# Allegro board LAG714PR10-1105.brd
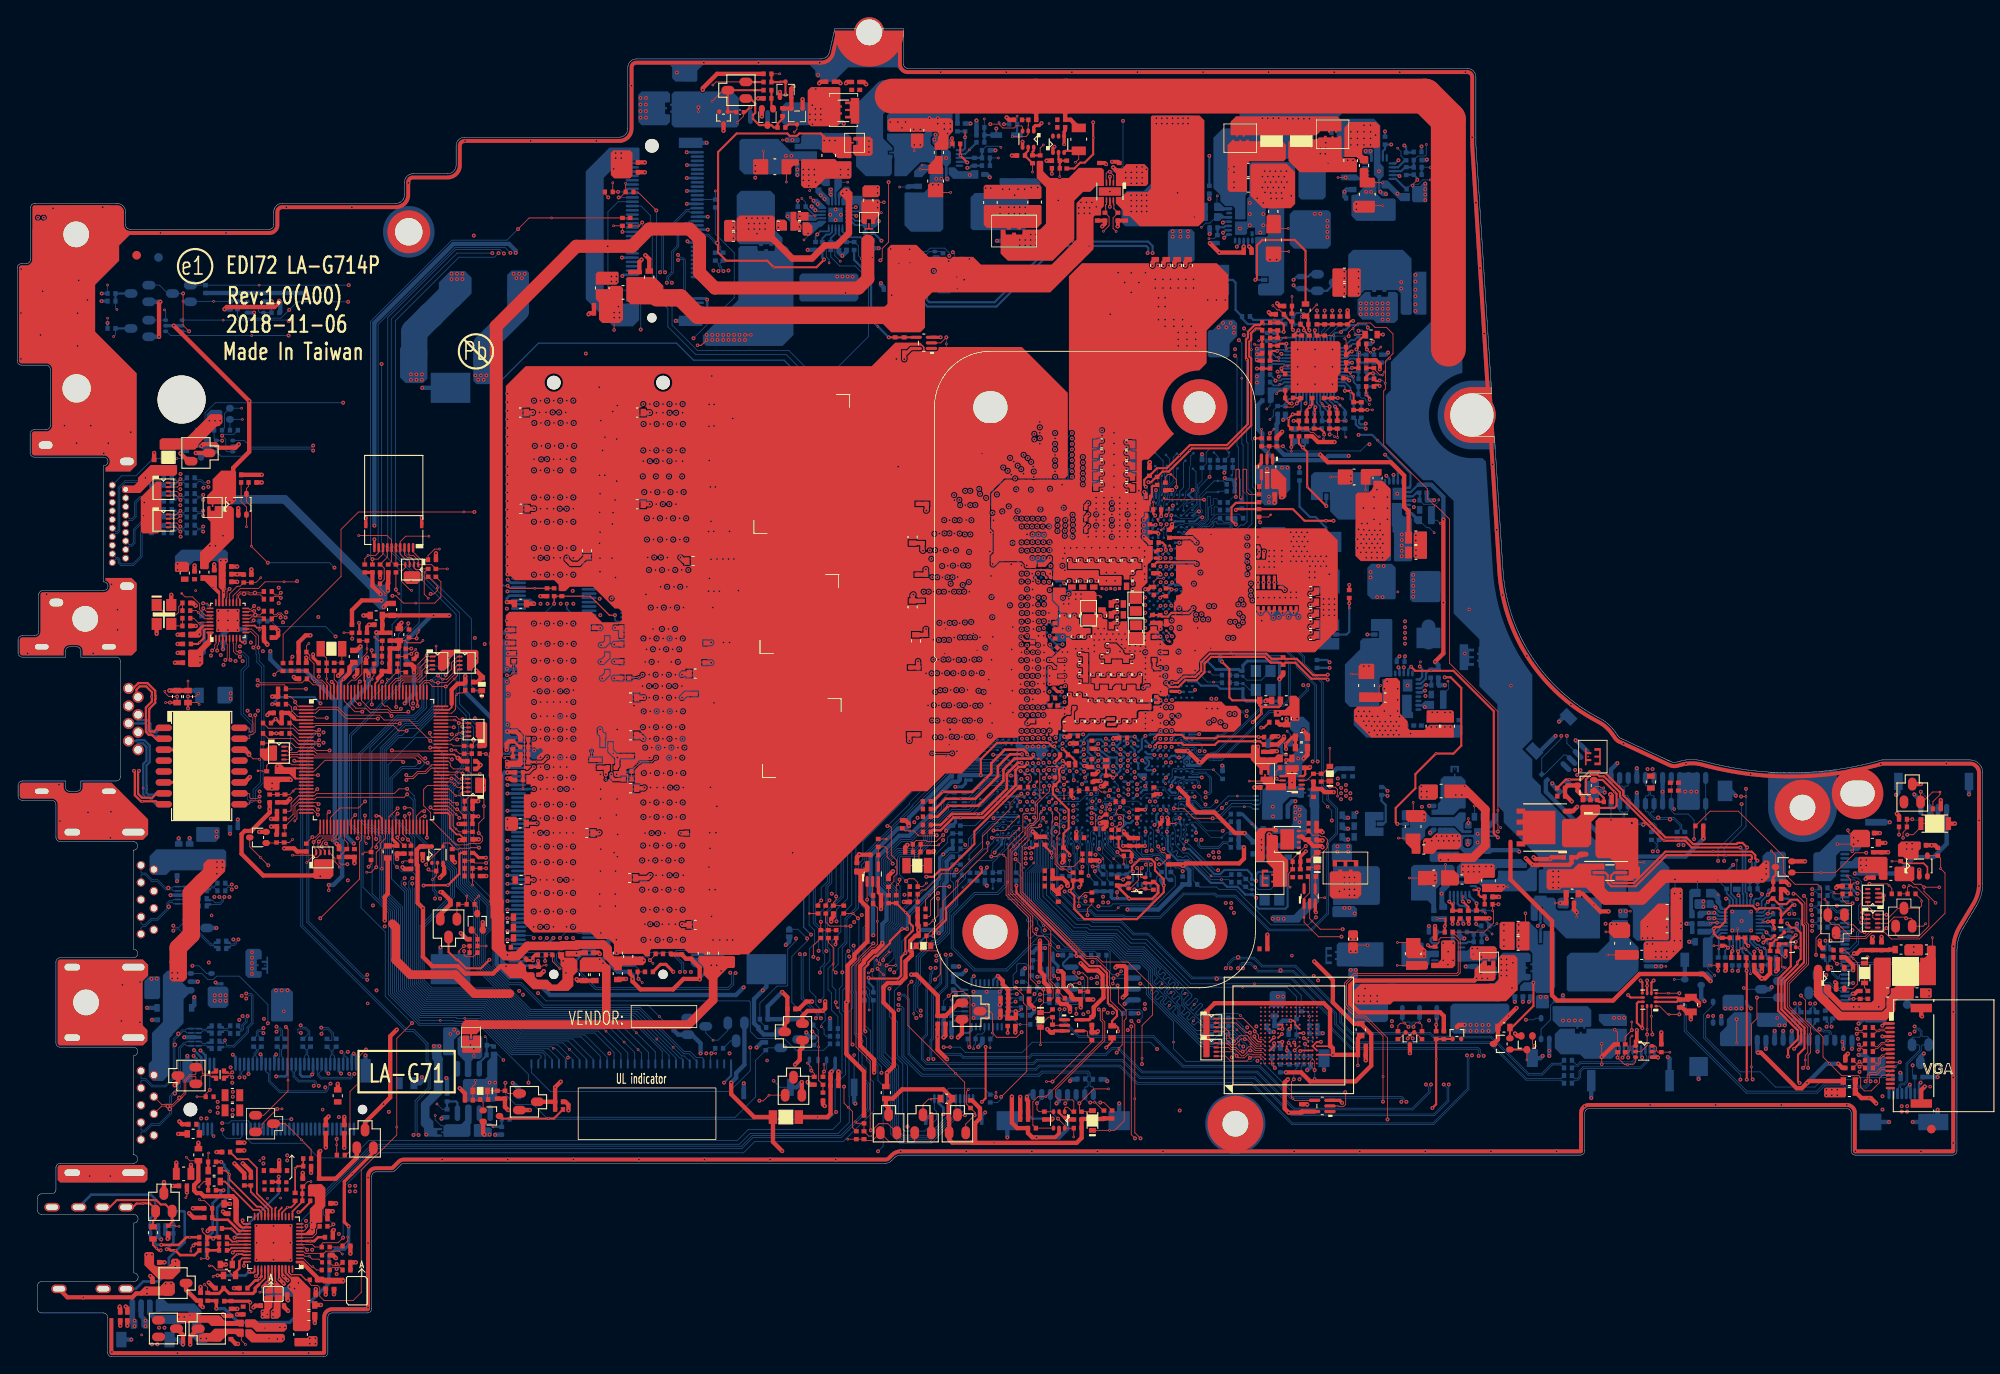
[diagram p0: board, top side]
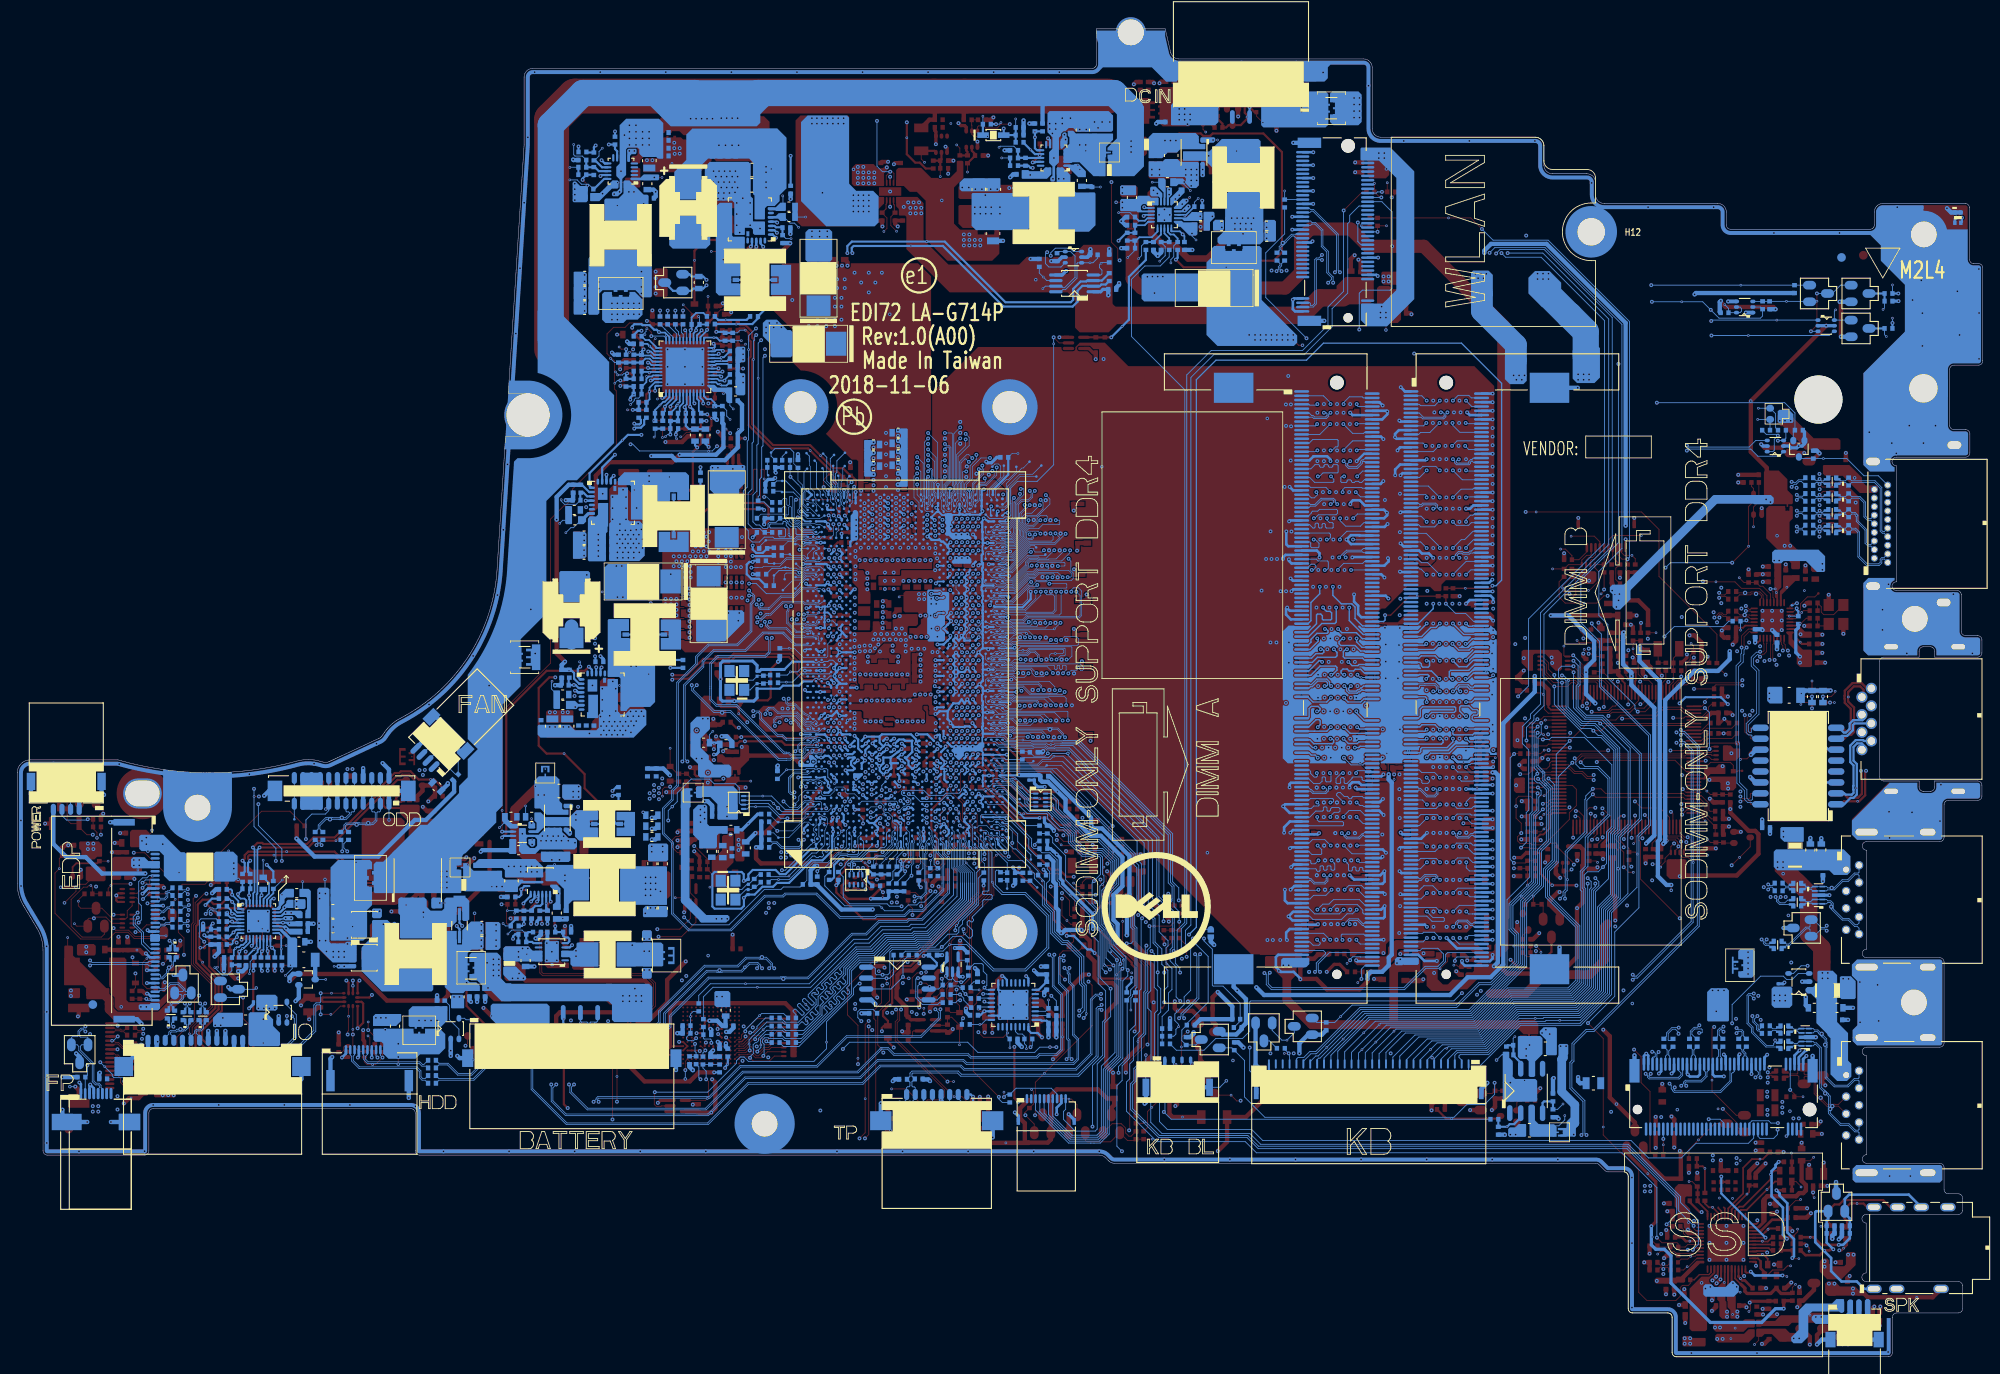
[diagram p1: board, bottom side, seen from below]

Outline 228.4 x 154.4 mm; copper layers: TOP, VCC, IN1, IN2, GND, BOTTOM. Coordinates in mm from the lower left corner of the outline.
Outline path: 0,126.6 arc(0.15,126.95) 0.5,127.1 1.05,127.1 arc(1.4,127.25) 1.55,127.6 1.55,133.6 arc(1.7,133.95) 2.05,134.1 11.6,134.1 arc(12.31,133.81) 12.6,133.1 12.6,131.6 arc(12.75,131.25) 13.1,131.1 29.3,131.1 arc(29.65,131.25) 29.8,131.6 29.8,133.1 arc(30.09,133.81) 30.8,134.1 44,134.1 arc(44.71,134.39) 45,135.1 45,136.55 arc(45.29,137.26) 46,137.55 50,137.55 arc(50.71,137.84) 51,138.55 51,140.8 arc(51.29,141.51) 52,141.8 69.95,141.8 arc(70.66,142.09) 70.95,142.8 70.95,149.9 arc(71.24,150.61) 71.95,150.9 93.4,150.9 arc(94.03,151.12) 94.38,151.68 95,154.4 97.5,154.4 97.5,154 arc(99,152.5) 100.5,154 100.5,154.4 103,154.4 103,150.3 arc(103.15,149.95) 103.5,149.8 168.5,149.8 arc(169.21,149.51) 169.5,148.8 169.5,140.9 171.34,112 169.05,112 arc(166.55,109.5) 169.05,107 171.66,107 172.64,91.52 arc(176,81.39) 183.91,74.22 arc(184.91,73.53) 185.72,72.62 185.99,72.22 arc(186.17,72.03) 186.39,71.89 192.15,69.2 arc(192.5,69.11) 192.85,69.14 193.21,69.25 arc(194.56,69.44) 195.9,69.26 arc(206.31,67.9) 216.69,69.4 226.9,69.4 arc(227.96,68.96) 228.4,67.9 228.4,55.03 arc(228.22,53.7) 227.69,52.46 226.11,49.84 arc(225.58,48.6) 225.4,47.27 225.4,23.95 arc(225.25,23.6) 224.9,23.45 213.6,23.45 arc(213.25,23.6) 213.1,23.95 213.1,28.35 arc(212.95,28.7) 212.6,28.85 182.65,28.85 arc(182.3,28.7) 182.15,28.35 182.15,23.95 arc(182,23.6) 181.65,23.45 102.66,23.45 arc(102.28,23.37) 101.96,23.16 101.59,22.79 arc(101.27,22.58) 100.89,22.5 44.96,22.5 arc(44.77,22.46) 44.6,22.35 43.9,21.65 arc(43.73,21.54) 43.54,21.5 41.7,21.5 arc(41.35,21.35) 41.2,21 41.2,5.6 arc(41.05,5.25) 40.7,5.1 36.6,5.1 arc(36.25,4.95) 36.1,4.6 36.1,0.5 arc(35.95,0.15) 35.6,0 11,0 arc(10.65,0.15) 10.5,0.5 10.5,4.6 arc(10.35,4.95) 10,5.1 2.85,5.1 arc(2.5,5.25) 2.35,5.6 2.35,8.25 arc(2.5,8.6) 2.85,8.75 13.55,8.75 arc(14.05,9.25) 13.55,9.75 13.55,15.55 arc(14.05,16.05) 13.55,16.55 2.85,16.55 arc(2.5,16.7) 2.35,17.05 2.35,18.45 arc(2.5,18.8) 2.85,18.95 4,18.95 arc(4.35,19.1) 4.5,19.45 4.5,22 arc(4.65,22.35) 5,22.5 13.5,22.5 arc(14,23) 13.5,23.5 13.5,35 arc(14,35.5) 13.5,36 5,36 arc(4.65,36.15) 4.5,36.5 4.5,45.9 arc(4.65,46.25) 5,46.4 13.5,46.4 arc(14,46.9) 13.5,47.4 13.5,58.9 arc(14,59.4) 13.5,59.9 5,59.9 arc(4.65,60.05) 4.5,60.4 4.5,64.2 arc(4.35,64.55) 4,64.7 0.6,64.7 arc(0.25,64.85) 0.1,65.2 0.1,66.45 arc(0.25,66.8) 0.6,66.95 5.6,66.95 5.6,66.25 arc(5.75,65.9) 6.1,65.75 6.9,65.75 arc(7.25,65.9) 7.4,66.25 7.4,66.95 11.5,66.95 arc(11.85,67.1) 12,67.45 12,80.85 arc(11.85,81.2) 11.5,81.35 7.4,81.35 7.4,82.05 arc(7.25,82.4) 6.9,82.55 6.1,82.55 arc(5.75,82.4) 5.6,82.05 5.6,81.35 0.6,81.35 arc(0.25,81.5) 0.1,81.85 0.1,83.35 arc(0.25,83.7) 0.6,83.85 2,83.85 arc(2.35,84) 2.5,84.35 2.5,88.6 arc(2.65,88.95) 3,89.1 10.05,89.1 arc(10.55,89.6) 10.05,90.1 10.05,103.6 arc(10.55,104.1) 10.05,104.6 2,104.6 arc(1.65,104.75) 1.5,105.1 1.5,107.3 arc(1.65,107.65) 2,107.8 3.35,107.8 arc(3.7,107.95) 3.85,108.3 3.85,114.8 arc(3.7,115.15) 3.35,115.3 0.5,115.3 arc(0.15,115.45) 0,115.8 0,126.6

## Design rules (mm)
net group AS-PROCHOT#: nets H_PROCHOT# H_PROCHOT#_R
net group AS-VCCST_PWRGOOD: nets H_VCCST_PWRGD VCCST_PWRGD
net group CLK_PCIE_NVME_4: nets CLK_PCIE_NVME_N4 CLK_PCIE_NVME_P4
net group CPU-DP: nets CPU_DP2_AUXN CPU_DP2_AUXP
net group CPU_DP1_CTRL_CLK: nets CPU_DP1_CTRL_CLK CPU_DP1_CTRL_DATA
net group CPU_DP2_0: nets CPU_DP2_N0 CPU_DP2_P0
net group CPU_DP2_0_C: nets CPU_DP2_N0_C CPU_DP2_P0_C
net group CPU_DP2_1: nets CPU_DP2_N1 CPU_DP2_P1
net group CPU_DP2_1_C: nets CPU_DP2_N1_C CPU_DP2_P1_C
net group CPU_DP2_AUX_C: nets CPU_DP2_AUXN_C CPU_DP2_AUXP_C
net group DDR_A_CLK0: nets DDR_A_CLK0 DDR_A_CLK#0
net group DDR_A_CLK1: nets DDR_A_CLK1 DDR_A_CLK#1
net group DDR_B_CLK0: nets DDR_B_CLK0 DDR_B_CLK#0
net group DDR_B_CLK1: nets DDR_B_CLK1 DDR_B_CLK#1
net group DDR_RESET: nets DDR4_DRAMRST# H_DRAMRST#
net group DMIC_EDP: nets DMIC_CLK_EDP DMIC_DATA_EDP
net group EDP_AUX: nets EDP_AUX EDP_AUX#
net group EDP_AUX_D: nets EDP_AUX_DN EDP_AUX_DP
net group EDP_TX0: nets EDP_TX0 EDP_TX0#
net group EDP_TX0_D: nets EDP_TX0_DN EDP_TX0_DP
net group EDP_TX1: nets EDP_TX1 EDP_TX1#
net group EDP_TX1_D: nets EDP_TX1_DN EDP_TX1_DP
net group HDA_CBN/CBP/CPVEE: nets CBP CPVEE
net group HDMI_CLK: nets HDMI_CLK HDMI_CLK#
net group HDMI_CLK_R: nets HDMI_CLK#_R HDMI_CLK_R
net group HDMI_CLK_R_C: nets HDMI_CLK#_R_C HDMI_CLK_R_C
net group HDMI_DATA0: nets HDMI_DATA0 HDMI_DATA0#
net group HDMI_DATA0_R: nets HDMI_DATA0#_R HDMI_DATA0_R
net group HDMI_DATA0_R_C: nets HDMI_DATA0#_R_C HDMI_DATA0_R_C
net group HDMI_DATA1: nets HDMI_DATA1 HDMI_DATA1#
net group HDMI_DATA1_R: nets HDMI_DATA1#_R HDMI_DATA1_R
net group HDMI_DATA1_R_C: nets HDMI_DATA1#_R_C HDMI_DATA1_R_C
net group HDMI_DATA2: nets HDMI_DATA2 HDMI_DATA2#
net group HDMI_DATA2_R: nets HDMI_DATA2#_R HDMI_DATA2_R
net group HDMI_DATA2_R_C: nets HDMI_DATA2#_R_C HDMI_DATA2_R_C
net group HDMI_DDC: nets DDC_CLK_HDMI DDC_DATA_HDMI
net group I2C: nets CLK_TP_SIO DAT_TP_SIO
net group I2C0_SCL_TCH_PAD: nets I2C0_SCL_TCH_PAD I2C0_SDA_TCH_PAD
net group I2C_SCL_TP: nets I2C_SCL_TP I2C_SDA_TP
net group LAN_MDI2: nets LAN_MDI2N LAN_MDI2P
net group LAN_MDI3: nets LAN_MDI3N LAN_MDI3P
net group MDO2: nets MDO2+ MDO2-
net group MDO3: nets MDO3+ MDO3-
net group NCT7718_DXP: nets NCT7718_DXN NCT7718_DXP
net group PCH_SMBCLK: nets PCH_SMBCLK PCH_SMBDATA
net group PCIE_CRX_NVMETX_9: nets PCIE_CRX_NVMETX_N9 PCIE_CRX_NVMETX_P9
net group PCIE_CRX_NVMETX_10: nets PCIE_CRX_NVMETX_N10 PCIE_CRX_NVMETX_P10
net group PCIE_CRX_NVMETX_11: nets PCIE_CRX_NVMETX_N11 PCIE_CRX_NVMETX_P11
net group PCIE_CRX_NVMETX_12: nets PCIE_CRX_NVMETX_N12 PCIE_CRX_NVMETX_P12
net group PCIE_CRX_WLANTX_6: nets PCIE_CRX_WLANTX_N6 PCIE_CRX_WLANTX_P6
net group PCIE_CTX_C_LANRX_5: nets PCIE_CTX_C_LANRX_N5 PCIE_CTX_C_LANRX_P5
net group PCIE_CTX_C_NVMERX_9: nets PCIE_CTX_C_NVMERX_N9 PCIE_CTX_C_NVMERX_P9
net group PCIE_CTX_C_NVMERX_11: nets PCIE_CTX_C_NVMERX_N11 PCIE_CTX_C_NVMERX_P11
net group PCIE_CTX_C_NVMERX_12: nets PCIE_CTX_C_NVMERX_N12 PCIE_CTX_C_NVMERX_P12
net group PCIE_CTX_C_WLANRX_6: nets PCIE_CTX_C_WLANRX_N6 PCIE_CTX_C_WLANRX_P6
net group PCIE_CTX_LANRX_5: nets PCIE_CTX_LANRX_N5 PCIE_CTX_LANRX_P5
net group PCIE_CTX_NVMERX_9: nets PCIE_CTX_NVMERX_N9 PCIE_CTX_NVMERX_P9
net group PCIE_CTX_NVMERX_10: nets PCIE_CTX_NVMERX_N10 PCIE_CTX_NVMERX_P10
net group PCIE_CTX_NVMERX_11: nets PCIE_CTX_NVMERX_N11 PCIE_CTX_NVMERX_P11
net group PCIE_CTX_NVMERX_12: nets PCIE_CTX_NVMERX_N12 PCIE_CTX_NVMERX_P12
net group SATA3_CRX_C_HDDTX_0: nets SATA3_CRX_C_HDDTX_N0 SATA3_CRX_C_HDDTX_P0
net group SATA3_CTX_C_HDDRX_0: nets SATA3_CTX_C_HDDRX_N0 SATA3_CTX_C_HDDRX_P0
net group SML0_SMBCLK: nets SML0_SMBCLK SML0_SMBDATA
net group THM_SML1_CLK: nets THM_SML1_CLK THM_SML1_DATA
net group USB3_CRX_DTX_1_C: nets USB3_CRX_DTX_N1_C USB3_CRX_DTX_P1_C
net group USB3_CTX_DRX_1: nets USB3_CTX_DRX_N1 USB3_CTX_DRX_P1
net group USB3_CTX_DRX_1_C: nets USB3_CTX_DRX_N1_C USB3_CTX_DRX_P1_C
net group USB3_CTX_DRX_1_R: nets USB3_CTX_DRX_N1_R USB3_CTX_DRX_P1_R
net group USB_CAMERA_EDP: nets USB_CAMERA_EDP USB_CAMERA_EDP#
net group USB_P5: nets USB_PN5 USB_PP5
net group USB_P6_R: nets USB_PN6_R USB_PP6_R
net group USB_P7: nets USB_PN7 USB_PP7
net group USB_P9: nets USB_PN9 USB_PP9
net group 15: nets XTAL24_IN_R
net group AS-BPM#[3:0]: nets XDP_OBS0_R XDP_OBS1_R XDP_OBS2_R XDP_OBS3_R
net group AS-CATERR#: nets H_CATERR#
net group AS-PECI: nets PECI_EC
net group AS-THERMTRIP#: nets H_THERMTRIP#
net group DDR_COMP_20_25: nets SM_RCOMP0 SM_RCOMP1 SM_RCOMP2
net group DDRA_D0: nets DDR_A_D0 DDR_A_D1 DDR_A_D2 DDR_A_D3 DDR_A_D4 DDR_A_D5 DDR_A_D6 DDR_A_D7
net group DDRA_D1: nets DDR_A_D8 DDR_A_D9 DDR_A_D10 DDR_A_D11 DDR_A_D12 DDR_A_D13 DDR_A_D14 DDR_A_D15
net group DDRA_D2: nets DDR_A_D16 DDR_A_D17 DDR_A_D18 DDR_A_D19 DDR_A_D20 DDR_A_D21 DDR_A_D22 DDR_A_D23
net group DDRA_D3: nets DDR_A_D24 DDR_A_D25 DDR_A_D26 DDR_A_D27 DDR_A_D28 DDR_A_D29 DDR_A_D30 DDR_A_D31
net group DDRA_D4: nets DDR_A_D32 DDR_A_D33 DDR_A_D34 DDR_A_D35 DDR_A_D36 DDR_A_D37 DDR_A_D38 DDR_A_D39
net group DDRA_D5: nets DDR_A_D40 DDR_A_D41 DDR_A_D42 DDR_A_D43 DDR_A_D44 DDR_A_D45 DDR_A_D46 DDR_A_D47
net group DDRA_D6: nets DDR_A_D48 DDR_A_D49 DDR_A_D50 DDR_A_D51 DDR_A_D52 DDR_A_D53 DDR_A_D54 DDR_A_D55
net group DDRA_D7: nets DDR_A_D56 DDR_A_D57 DDR_A_D58 DDR_A_D59 DDR_A_D60 DDR_A_D61 DDR_A_D62 DDR_A_D63
net group DDRA_DQS: nets DDR_A_DQS0 DDR_A_DQS1 DDR_A_DQS2 DDR_A_DQS3 DDR_A_DQS4 DDR_A_DQS5 DDR_A_DQS6 DDR_A_DQS7 DDR_A_DQS#0 DDR_A_DQS#1 DDR_A_DQS#2 DDR_A_DQS#3 DDR_A_DQS#4 DDR_A_DQS#5 DDR_A_DQS#6 DDR_A_DQS#7
net group DDRADD_10/11_19/20: nets DDR_A_ACT# DDR_A_ALERT# DDR_A_BG0 DDR_A_BG1 DDR_A_BS0 DDR_A_BS1 DDR_A_CAS# DDR_A_MA0 DDR_A_MA1 DDR_A_MA2 DDR_A_MA3 DDR_A_MA4 DDR_A_MA5 DDR_A_MA6 DDR_A_MA7 DDR_A_MA8 DDR_A_MA9 DDR_A_MA10 DDR_A_MA11 DDR_A_MA12 DDR_A_MA13 DDR_A_PAR DDR_A_RAS# DDR_A_WE# DDR_B_ACT# DDR_B_ALERT# DDR_B_BG0 DDR_B_BG1 DDR_B_BS0 DDR_B_BS1 DDR_B_CAS# DDR_B_MA0 DDR_B_MA1 DDR_B_MA2 DDR_B_MA3 DDR_B_MA4 DDR_B_MA5 DDR_B_MA6 DDR_B_MA7 DDR_B_MA8 DDR_B_MA9 DDR_B_MA10 DDR_B_MA11 DDR_B_MA12 DDR_B_MA13 DDR_B_PAR DDR_B_RAS# DDR_B_WE#
net group DDRB_D0: nets DDR_B_D0 DDR_B_D1 DDR_B_D2 DDR_B_D3 DDR_B_D4 DDR_B_D5 DDR_B_D6 DDR_B_D7
net group DDRB_D1: nets DDR_B_D8 DDR_B_D9 DDR_B_D10 DDR_B_D11 DDR_B_D12 DDR_B_D13 DDR_B_D14 DDR_B_D15
net group DDRB_D2: nets DDR_B_D16 DDR_B_D17 DDR_B_D18 DDR_B_D19 DDR_B_D20 DDR_B_D21 DDR_B_D22 DDR_B_D23
net group DDRB_D3: nets DDR_B_D24 DDR_B_D25 DDR_B_D26 DDR_B_D27 DDR_B_D28 DDR_B_D29 DDR_B_D30 DDR_B_D31
net group DDRB_D4: nets DDR_B_D32 DDR_B_D33 DDR_B_D34 DDR_B_D35 DDR_B_D36 DDR_B_D37 DDR_B_D38 DDR_B_D39
net group DDRB_D5: nets DDR_B_D40 DDR_B_D41 DDR_B_D42 DDR_B_D43 DDR_B_D44 DDR_B_D45 DDR_B_D46 DDR_B_D47
net group DDRB_D6: nets DDR_B_D48 DDR_B_D49 DDR_B_D50 DDR_B_D51 DDR_B_D52 DDR_B_D53 DDR_B_D54 DDR_B_D55
net group DDRB_D7: nets DDR_B_D56 DDR_B_D57 DDR_B_D58 DDR_B_D59 DDR_B_D60 DDR_B_D61 DDR_B_D62 DDR_B_D63
net group DDRB_DQS: nets DDR_B_DQS0 DDR_B_DQS1 DDR_B_DQS2 DDR_B_DQS3 DDR_B_DQS4 DDR_B_DQS5 DDR_B_DQS6 DDR_B_DQS7 DDR_B_DQS#0 DDR_B_DQS#1 DDR_B_DQS#2 DDR_B_DQS#3 DDR_B_DQS#4 DDR_B_DQS#5 DDR_B_DQS#6 DDR_B_DQS#7
net group DDRCTL_10/11_19/20: nets DDR_A_CKE0 DDR_A_CKE1 DDR_A_CKE2 DDR_A_CKE3 DDR_A_CS#0 DDR_A_CS#1 DDR_A_ODT0 DDR_A_ODT1 DDR_B_CKE0 DDR_B_CKE1 DDR_B_CKE2 DDR_B_CKE3 DDR_B_CS#0 DDR_B_CS#1 DDR_B_ODT0 DDR_B_ODT1
net group EDP_COMP: nets EDP_COMP
net group EMMC: nets EMMC_CLK EMMC_DATA0 EMMC_DATA1 EMMC_DATA2 EMMC_DATA3 EMMC_DATA4 EMMC_DATA5 EMMC_DATA6 EMMC_DATA7 EMMC_RCLK
net group ESPI: nets ESPI_CS# ESPI_RESET# PCH_ESPI_CLK PCH_ESPI_IO0 PCH_ESPI_IO1 PCH_ESPI_IO2 PCH_ESPI_IO3
net group HDA SPEAKER: nets AUD_SPK_L+ AUD_SPK_L- AUD_SPK_R+ AUD_SPK_R+_C AUD_SPK_R- AUD_SPK_R-_C
net group HDA_ANALOG IO: nets AUD_HP1_JACK_L AUD_HP1_JACK_L1 AUD_HP1_JACK_R AUD_HP1_JACK_R1 CBN HPOUT_L HPOUT_R LINE1-L_C LINE1-L_R LINE1_L LINE1_R
net group HIGH DEFINITION AUDIO: nets DMIC_CLK HDA_BIT_CLK HDA_CODEC_BITCLK HDA_CODEC_RST# HDA_CODEC_SDOUT HDA_CODEC_SYNC HDA_RST# HDA_SDIN0 HDA_SDOUT HDA_SYNC
net group KB: nets KSI0 KSI1 KSI2 KSI3 KSI4 KSI5 KSI6 KSI7 KSO0 KSO1 KSO2 KSO3 KSO4 KSO5 KSO6 KSO7 KSO8 KSO9 KSO10 KSO11 KSO12 KSO13 KSO14 KSO15 KSO16
net group MDI: nets LAN_MDI0N LAN_MDI0P LAN_MDI1N LAN_MDI1P MDO0+ MDO0- MDO1+ MDO1-
net group PCIE: nets PCIE_CRX_C_LANTX_N5 PCIE_CRX_C_LANTX_P5 PCIE_CRX_LANTX_N5 PCIE_CRX_LANTX_P5 PCIE_CTX_C_NVMERX_N10 PCIE_CTX_C_NVMERX_P10 PCIE_CTX_WLANRX_N6 PCIE_CTX_WLANRX_P6
net group PLATFORM CLOCK-DIFF: nets CLK_ITPXDP_N CLK_ITPXDP_P CLK_PCIE_LAN_N2 CLK_PCIE_LAN_P2 CLK_PCIE_WLAN_N1 CLK_PCIE_WLAN_P1
net group RTC: nets PCH_RTCRST# PCH_RTCX1 PCH_RTCX2 SRTCRST# SUSCLK SUSCLK_EC SUSCLK_WLAN
net group SATA_HDD: nets SATA3_CRX_HDDTX_N0 SATA3_CRX_HDDTX_P0 SATA3_CTX_HDDRX_N0 SATA3_CTX_HDDRX_P0
net group SATA_ODD: nets SATA_CRX_C_ODDTX_N1 SATA_CRX_C_ODDTX_P1 SATA_CRX_ODDTX_N1 SATA_CRX_ODDTX_P1 SATA_CTX_C_ODDRX_N1 SATA_CTX_C_ODDRX_P1 SATA_CTX_ODDRX_N1 SATA_CTX_ODDRX_P1
net group SMBUS: nets CLK_SMB DAT_SMB MEM_SMBCLK MEM_SMBDATA PBAT_CHG_SMBCLK PBAT_CHG_SMBDAT SML1_SMBCLK SML1_SMBDATA
net group SPI: nets PCH_SPI_CLK PCH_SPI_CLK_R PCH_SPI_CLK_TPM PCH_SPI_CS#0 PCH_SPI_CS#2 PCH_SPI_D0 PCH_SPI_D0_R PCH_SPI_D1 PCH_SPI_D1_R PCH_SPI_D2 PCH_SPI_D2_R PCH_SPI_D3 PCH_SPI_D3_R
net group SRCCLKREQ/ CLKOUT_LPC: nets CLK_PCIE_LAN_REQ# CLK_PCIE_LAN_REQ#_R CLK_PCIE_WLAN_REQ# CLK_PCIE_WLAN_REQ#_R
net group SVID: nets H_CPU_SVIDALRT# VIDALERT_N VIDSCLK VIDSOUT
net group USB20: nets USB_PN1 USB_PN1_R USB_PN2 USB_PN2_R USB_PN3 USB_PN3_R USB_PN6 USB_PN8 USB_PN8_TPNL USB_PP1 USB_PP1_R USB_PP2 USB_PP2_R USB_PP3 USB_PP3_R USB_PP6 USB_PP8 USB_PP8_TPNL
net group USB30: nets USB3_CRX_DTX_N1 USB3_CRX_DTX_N3 USB3_CRX_DTX_N3_C USB3_CRX_DTX_P1 USB3_CRX_DTX_P3 USB3_CRX_DTX_P3_C USB3_CTX_DRX_N3 USB3_CTX_DRX_N3_C USB3_CTX_DRX_N3_R USB3_CTX_DRX_P3 USB3_CTX_DRX_P3_C USB3_CTX_DRX_P3_R
net group XCLK_BIASREF: nets XCLK_BIASREF
net group XDP: nets CPU_XDP_TCK0 PCH_JTAG_TCK1 PCH_RSMRST#_Q SOC_XDP_TDI SOC_XDP_TDO SOC_XDP_TMS SOC_XDP_TRST# XDP_HOOK0 XDP_ITP_PMODE XDP_PRDY# XDP_PREQ# XDP_PRSENT_CPU XDP_SPI_IO2 XDP_SPI_SI
net group XDP_OBS_CLK_1P: nets CFG16 CFG17 CFG18 CFG19
net group XDP_OBSDATA: nets CFG0 CFG1 CFG2 CFG3 CFG4 CFG5 CFG6 CFG7 CFG8 CFG9 CFG10 CFG11 CFG12 CFG13 CFG14 CFG15 CFG_RCOMP
net group XTAL24_IN/OUT: nets XTAL24_IN XTAL24_OUT XTAL24_OUT_R
nets with their own width: min track width 0.254; nets +1.0V_APLL +1.0V_VCCST +1.0V_VCCST_C +1.0V_VCCSTG +1.8V_PRIM +3.3V_ALW_DSW +3.3V_SPI +3VALW_EC +TP_VDD
nets with their own width: min track width 0.305; nets LDO3_CAP
nets with their own width: min track width 0.381; nets +1.8V_AVDD +1.8V_CPVDD N17283936 PCIE_RCOMPN PCIE_RCOMPP
nets with their own width: min track width 0.508; nets +1.0V_AMPHYPLL +1.0V_MPHYGT +1.0V_PRIM +1.0VS_VCCIO +1.2V_DDR +1.2VP +1.8V_EMMC +2.5VP +3V_DVDD +3V_EMMC +3VALW +3VALW_PCH +3VALWP +3VLP +3VS +3VS_CAM +5V_KB_BL +5VALW +5VALWP +5VS +19VB +DC_IN +FP_VCC +LAN_VDD33 +RTC_CELL +V_DDR_REFA +V_DDR_REFA_R +VCC_CORE +VCC_GT +VCC_GT_AK52 +VCC_SA AUD_AGND EC_AGND GND HDMI_PLL_GND N124752685
nets with their own width: min track width 1.016; nets +2.5V_MEM +5V_HDD +5V_HDMI +TPAN_VDD +TPAN_VDD_F AUD_SPK_L+_C AUD_SPK_L-_C RING2 RING2_R SLEEVE SLEEVE_R
nets with their own width: min track width 1.524; nets +0.6VSP +5V_AVDD +5VS_ODD +DCBAT_LCD
nets with their own width: min track width 2.032; nets +3.3V_WLAN +LCDVDD_LCD USB30_VCCA
nets with their own width: min track width 2.54; nets +5V_PVDD

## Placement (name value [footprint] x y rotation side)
C1  0.47U_0402_6.3V6K  [C_0402]  89.49 40.44 0 top
C2  0.1U_0402_16V7K  [C_0402]  216.63 57.75 90 top
C3  1U_0402_10V6K  [C_0402]  215.68 56.63 270 top
C4  0.1U_0603_50V7K  [C_0603]  214.85 59.75 0 top
C5  1000P_0402_50V7K  [C_0402]  214.84 60.89 0 top
C6  0.1U_0402_16V7K  [C_0402]  209.44 52.68 0 bottom
C7  0.1U_0402_16V7K  [C_0402]  209.44 51.79 0 bottom
C8  0.1U_0402_16V7K  [C_0402]  209.44 50.84 0 bottom
C9  0.1U_0402_16V7K  [C_0402]  209.44 49.95 0 bottom
C10  0.1U_0402_16V7K  [C_0402]  209.44 53.64 0 bottom
C11  0.1U_0402_16V7K  [C_0402]  209.44 54.52 0 bottom
C12  10P_0402_50V8J  [C_0402]  215.68 57.75 90 top
C14  33P_0402_50V8J  [C_0402]  215.55 47.29 90 top
C15  4.7U_0402_6.3V6M  [C_0402]  216.63 47.29 90 top
C16  10P_0402_50V8J  [C_0402]  214.16 41.62 90 top
C17  1U_0402_6.3V6K  [C_0402]  220.87 59.48 0 top
C18  .1U_0402_16V7K  [C_0402]  98.4 26.22 270 top
C19  0.1U_0402_16V7K  [C_0402]  117.46 28.49 180 top
C21  0.1U_0402_16V7K  [C_0402]  101.61 124.11 180 bottom
C22  470P_0603_50V8J  [C_0603]  149.2 124.2 90 bottom
C23  2200P_0402_50V7K  [C_0402]  101.51 125.08 90 bottom
C26  10P_0402_50V8J  [C_0402]  124.1 32.3 180 bottom
C27  10P_0402_50V8J  [C_0402]  125.01 32.27 0 bottom
C30  22U_0603_6.3V6M  [C_0603]  180.14 66.78 225 bottom
C31  1U_0402_10V6K  [C_0402]  209.79 46.62 90 top
C32  0.1U_0402_16V7K  [C_0402]  52 55.91 0 top
C33  100P_0402_50V8J  [C_0402]  52 56.8 0 top
C34  .1U_0402_16V7K  [C_0402]  94.51 31.52 0 top
C35  100P_0402_50V8J  [C_0402]  124.88 36.81 90 top
C36  100P_0402_50V8J  [C_0402]  144.32 101.18 0 top
C37  0.1U_0402_16V7K  [C_0402]  217.95 32.32 0 bottom
C38  1U_0402_6.3V6K  [C_0402]  62.51 29.65 0 top
C39  22P_0402_50V8J  [C_0402]  52.94 29.84 180 top
C40  0.1U_0402_25V6  [C_0402]  55.79 30.93 270 top
C41  1U_0402_10V6K  [C_0402]  11.41 122.74 180 bottom
CA1  10U_0603_10V6M  [C_0603]  33.18 4.76 0 top
CA2  .1U_0402_16V7K  [C_0402]  32.3 7.22 180 top
CA3  10U_0603_10V6M  [C_0603]  33.18 6.03 0 top
CA4  .1U_0402_16V7K  [C_0402]  33.77 7.22 0 top
CA5  10U_0402_6.3V6M  [C_0402]  35.48 17.84 0 top
CA6  .1U_0402_16V7K  [C_0402]  35.14 16.92 0 top
CA7  .1U_0402_16V7K  [C_0402]  33.18 19.79 90 top
CA9  6.8P_0402_50V  [C_0402]  37.8 10.98 0 top
CA10  .1U_0402_16V7K  [C_0402]  25.45 16.63 180 top
CA11  10U_0603_10V6M  [C_0603]  25.43 17.78 180 top
CA12  10U_0402_6.3V6M  [C_0402]  23.97 7.98 180 top
CA13  10U_0402_6.3V6M  [C_0402]  26.26 5.84 270 top
CA14  .1U_0402_16V7K  [C_0402]  24.86 6.49 270 top
CA15  10U_0402_6.3V6M  [C_0402]  36.81 8.8 270 top
CA16  .1U_0402_16V7K  [C_0402]  35.85 8.83 270 top
CA17  .1U_0402_16V7K  [C_0402]  35.14 16.04 0 top
CA20  10U_0402_6.3V6M  [C_0402]  21.75 16.19 0 top
CA21  10U_0402_6.3V6M  [C_0402]  25.84 7.98 0 top
CA22  10U_0402_6.3V6M  [C_0402]  36.67 13.9 180 top
CA23  2.2U_0402_6.3V6M  [C_0402]  23.78 14.92 180 top
CA24  1U_0603_16V7  [C_0603]  25.37 9.46 180 top
CA25  1U_0603_16V7  [C_0603]  23.59 10.73 0 top
CA26  10U_0402_6.3V6M  [C_0402]  24.74 23.81 180 top
CA27  1000P_0402_50V7K  [C_0402]  30.09 5.95 0 top
CA28  1000P_0402_50V7K  [C_0402]  29.22 5.95 180 top
CA29  1000P_0402_50V7K  [C_0402]  24.83 3.84 90 top
CA30  1000P_0402_50V7K  [C_0402]  24.83 2.98 270 top
CA31  0.1U_0402_16V7K  [C_0402]  32.29 19.06 270 top
CA32  10U_0603_10V6M  [C_0603]  23.59 20.38 180 top
CA33  10U_0603_10V6M  [C_0603]  23.59 21.65 180 top
CA34  100P_0402_50V8J  [C_0402]  15.45 15.24 0 bottom
CA35  100P_0402_50V8J  [C_0402]  18.14 15.24 180 bottom
CA36  680P_0402_50V8J  [C_0402]  15.73 7.79 90 top
CA37  680P_0402_50V8J  [C_0402]  15.58 10.98 0 top
CA38  33P_0402_50V8J  [C_0402]  38.72 12.89 180 top
CA40  10P_0402_50V8J  [C_0402]  37.8 10.09 0 top
CA41  680P_0402_50V8J  [C_0402]  28.66 21.65 0 top
CA42  680P_0402_50V8J  [C_0402]  31.35 21.65 180 top
CC1  0.1U_0402_16V7K  [C_0402]  103.08 116.74 180 top
CC2  33P_0402_50V8J  [C_0402]  116.81 44.51 270 bottom
CC3  0.1U_0402_25V6  [C_0402]  122.44 46.7 180 bottom
CC4  1U_0402_6.3V6K  [C_0402]  87.03 38.29 180 bottom
CC5  1U_0402_6.3V6K  [C_0402]  92.57 36.25 90 bottom
CC6  15P_0201_25V8J  [C_0201]  142.43 79.13 90 bottom
CC7  15P_0201_25V8J  [C_0201]  142.43 78.27 270 bottom
CC8  6.8P_0402_50V8C  [C_0402]  104.95 58.7 0 top
CC9  6.8P_0402_50V8C  [C_0402]  104.09 58.7 180 top
CC10  1U_0402_6.3V6K  [C_0402]  99.46 53.65 0 top
CC11  0.1U_0402_10V7K  [C_0402]  97.57 56.5 90 top
CC12  0.1U_0402_16V7K  [C_0402]  124.88 39.51 270 top
CC13  0.1U_0402_16V7K  [C_0402]  146.12 101.19 270 top
CC14  1U_0402_6.3V6K  [C_0402]  120.3 38.62 270 top
CC15  100P_0402_50V8J  [C_0402]  138.6 103.4 0 bottom
CC17  12P_0201_25V8J  [C_0201]  143.47 54.33 270 bottom
CC18  12P_0201_25V8J  [C_0201]  143.44 54.94 90 bottom
CC26  10U_0402_6.3V6M  [C_0402]  104.68 80.15 270 top
CC27  10U_0402_6.3V6M  [C_0402]  105.57 83.96 270 top
CC28  10U_0402_6.3V6M  [C_0402]  105.19 94.6 90 top
CC29  10U_0402_6.3V6M  [C_0402]  104.68 72.37 90 top
CC30  10U_0402_6.3V6M  [C_0402]  103.67 72.37 90 top
CC31  10U_0402_6.3V6M  [C_0402]  103.79 80.15 270 top
CC32  1U_0402_6.3V6K  [C_0402]  104.56 90.94 270 top
CC33  1U_0402_6.3V6K  [C_0402]  117.99 83.08 90 top
CC34  1U_0402_6.3V6K  [C_0402]  105.19 87.89 270 top
CC35  1U_0402_6.3V6K  [C_0402]  104.68 99.17 90 top
CC36  22U_0603_6.3V6M  [C_0603]  104.43 83.94 270 top
CC37  22U_0603_6.3V6M  [C_0603]  104.05 87.88 270 top
CC38  22U_0603_6.3V6M  [C_0603]  104.05 94.61 90 top
CC39  10U_0402_6.3V6M  [C_0402]  105.69 99.16 90 top
CC40  1U_0402_6.3V6K  [C_0402]  118.04 73.94 0 top
CC41  1U_0402_6.3V6K  [C_0402]  144.83 69.42 90 top
CC42  1U_0402_6.3V6K  [C_0402]  145.5 73.78 0 top
CC43  1U_0402_6.3V6K  [C_0402]  105.57 90.94 270 top
CC44  1U_0402_6.3V6K  [C_0402]  145.73 69.42 90 top
CC45  1U_0402_6.3V6K  [C_0402]  120.6 76.61 180 top
CC46  1U_0402_6.3V6K  [C_0402]  120.85 82.46 225 top
CC47  1U_0402_6.3V6K  [C_0402]  120.02 75.73 270 top
CC48  1U_0402_6.3V6K  [C_0402]  120.91 75.73 270 top
CC49  10U_0402_6.3V6M  [C_0402]  120.59 83.52 90 top
CC50  10U_0402_6.3V6M  [C_0402]  120.59 85.29 90 top
CC51  1U_0402_6.3V6K  [C_0402]  119.4 56.51 0 top
CC52  1U_0402_6.3V6K  [C_0402]  119.4 55.62 0 top
CC53  1U_0402_6.3V6K  [C_0402]  119.4 54.73 0 top
CC54  1U_0402_6.3V6K  [C_0402]  120.98 52.91 90 top
CC55  1U_0402_6.3V6K  [C_0402]  123.1 70.4 90 top
CC56  1U_0402_6.3V6K  [C_0402]  119.41 59.55 90 top
CC57  1U_0402_6.3V6K  [C_0402]  124.88 69.48 270 top
CC58  1U_0402_6.3V6K  [C_0402]  128.96 71.95 180 top
CC59  47U_0603_6.3V6M  [C_0603]  146.41 58.03 90 bottom
CC60  1U_0402_6.3V6K  [C_0402]  128.55 64.56 180 top
CC61  0.5P_0402_50V8  [C_0402]  122.09 69.99 180 top
CC62  1U_0402_6.3V6K  [C_0402]  124.88 71.64 270 top
CC63  1U_0402_6.3V6K  [C_0402]  123.24 72.19 180 top
CC67  1U_0402_6.3V6K  [C_0402]  146.74 62.84 0 bottom
CC68  1U_0402_6.3V6K  [C_0402]  123.4 65.81 180 top
CC69  0.1U_0201_6.3V6K  [C_0201]  109.62 62.64 180 bottom
CC70  0.1U_0201_6.3V6K  [C_0201]  110.21 67.64 270 bottom
CC71  1U_0201_6.3V6M  [C_0201]  110.84 67.64 270 bottom
CC72  1U_0402_6.3V6K  [C_0402]  130.18 59.39 90 top
CC73  0.1U_0402_10V7K  [C_0402]  145.35 58.2 90 bottom
CC75  1U_0402_6.3V6K  [C_0402]  132.08 66.21 270 top
CC76  47U_0603_6.3V6M  [C_0603]  148.53 72.04 0 top
CC77  22U_0603_6.3V6M  [C_0603]  144.37 76.32 0 top
CC78  0.1U_0402_10V7K  [C_0402]  125 66.83 90 top
CC79  1U_0402_6.3V6K  [C_0402]  146.74 63.73 0 bottom
CC82  0.5P_0402_50V8  [C_0402]  126.53 67.57 270 top
CC83  0.1U_0603_25V7K  [C_0603]  147.51 74.89 270 top
CC84  47U_0603_6.3V6M  [C_0603]  146.75 71.21 180 bottom
CC85  1U_0402_6.3V6K  [C_0402]  149.1 55.77 90 top
CC86  1U_0402_6.3V6K  [C_0402]  123.97 60.35 180 top
CC87  1U_0402_6.3V6K  [C_0402]  129.29 59.4 90 top
CC88  10P_0402_50V8J  [C_0402]  108.71 60.85 90 bottom
CC90  100P_0402_50V8J  [C_0402]  103.06 118.53 270 top
CC91  10P_0402_50V8J  [C_0402]  94.84 52.46 270 top
CD1  10U_0603_6.3V6M~D  [C_0603]  79.66 46.22 90 top
CD2  10U_0603_6.3V6M~D  [C_0603]  80.93 46.22 90 top
CD3  1U_0402_6.3V6K~D  [C_0402]  82.93 46.27 90 top
CD4  1U_0402_6.3V6K~D  [C_0402]  82.04 46.27 90 top
CD5  1U_0402_6.3V6K~D  [C_0402]  72.04 46.21 90 top
CD6  10U_0603_6.3V6M~D  [C_0603]  69.79 45.27 270 top
CD7  10U_0603_6.3V6M~D  [C_0603]  69.79 46.22 90 top
CD8  10U_0603_6.3V6M~D  [C_0603]  71 45.84 90 top
CD9  0.1U_0402_16V7K~D  [C_0402]  77.22 46.78 90 top
CD10  2.2U_0402_6.3V6M  [C_0402]  78.3 46.28 90 top
CD11  1U_0402_6.3V6K~D  [C_0402]  77.81 60.89 0 top
CD12  1U_0402_6.3V6K~D  [C_0402]  78.81 77.07 90 top
CD13  1U_0402_6.3V6K~D  [C_0402]  79.99 82.99 180 top
CD14  1U_0402_6.3V6K~D  [C_0402]  77.92 77.07 90 top
CD15  1U_0402_6.3V6K~D  [C_0402]  70.19 80.83 0 top
CD16  1U_0402_6.3V6K~D  [C_0402]  70.19 82.86 0 top
CD17  1U_0402_6.3V6K~D  [C_0402]  70.19 84.77 0 top
CD18  1U_0402_6.3V6K~D  [C_0402]  70.19 83.88 0 top
CD19  10U_0603_6.3V6M~D  [C_0603]  71.99 72.25 180 top
CD20  10U_0603_6.3V6M~D  [C_0603]  78.08 79.43 0 top
CD21  10U_0603_6.3V6M~D  [C_0603]  71.86 55.68 180 top
CD22  10U_0603_6.3V6M~D  [C_0603]  77.82 92.51 0 top
CD23  10U_0603_6.3V6M~D  [C_0603]  72.74 109.79 180 top
CD24  10U_0603_6.3V6M~D  [C_0603]  78.08 50.22 0 top
CD25  10U_0603_6.3V6M~D  [C_0603]  71.98 66.1 180 top
CD26  10U_0603_6.3V6M~D  [C_0603]  71.98 76.64 180 top
CD27  330U_D2_2V_Y  [C_D2]  86.12 124.26 0 bottom
CD28  0.1U_0402_16V7K~D  [C_0402]  71.38 69.85 270 top
CD29  0.1U_0402_16V7K~D  [C_0402]  63.28 88.44 90 top
CD30  0.022U_0402_25V7K  [C_0402]  67.63 68.49 90 top
CD31  1U_0402_6.3V6K~D  [C_0402]  56.44 47.62 0 top
CD32  10U_0603_6.3V6M~D  [C_0603]  56.26 49.9 0 top
CD33  10U_0603_6.3V6M~D  [C_0603]  56.26 51.11 0 top
CD34  10U_0603_6.3V6M~D  [C_0603]  56.26 48.69 0 top
CD35  1U_0402_6.3V6K~D  [C_0402]  66.93 46.08 90 top
CD36  1U_0402_6.3V6K~D  [C_0402]  65.98 46.08 90 top
CD37  10U_0603_6.3V6M~D  [C_0603]  67.12 45.14 270 top
CD38  10U_0603_6.3V6M~D  [C_0603]  65.85 45.14 270 top
CD39  0.1U_0402_16V7K~D  [C_0402]  58.51 45.58 45 top
CD40  2.2U_0402_6.3V6M  [C_0402]  64.12 45.91 90 top
CD41  1U_0402_6.3V6K~D  [C_0402]  57.62 82.99 0 top
CD42  1U_0402_6.3V6K~D  [C_0402]  57.62 84.51 0 top
CD43  1U_0402_6.3V6K~D  [C_0402]  68.08 72.19 0 top
CD44  1U_0402_6.3V6K~D  [C_0402]  79.87 80.7 180 top
CD45  1U_0402_6.3V6K~D  [C_0402]  68.56 79.56 180 top
CD46  1U_0402_6.3V6K~D  [C_0402]  68.56 81.59 180 top
CD47  1U_0402_6.3V6K~D  [C_0402]  68.56 83.5 180 top
CD48  1U_0402_6.3V6K~D  [C_0402]  67.04 84.77 180 top
CD49  10U_0603_6.3V6M~D  [C_0603]  66.9 60.89 180 top
CD50  10U_0603_6.3V6M~D  [C_0603]  72.74 99.12 180 top
CD51  10U_0603_6.3V6M~D  [C_0603]  57.79 87.56 0 top
CD52  10U_0603_6.3V6M~D  [C_0603]  59.25 98.61 180 top
CD53  10U_0603_6.3V6M~D  [C_0603]  59.15 109.79 180 top
CD54  10U_0603_6.3V6M~D  [C_0603]  59.15 62.03 180 top
CD55  10U_0603_6.3V6M~D  [C_0603]  66.23 93.01 90 top
CD56  10U_0603_6.3V6M~D  [C_0603]  59.27 55.44 180 top
CD58  0.1U_0402_16V7K~D  [C_0402]  59.39 69.14 180 top
CD59  0.022U_0402_25V7K  [C_0402]  57.6 71.57 270 top
CE1  0.1U_0402_10V7K  [C_0402]  44.19 79.69 180 top
CE2  0.1U_0402_10V7K  [C_0402]  42.38 81.46 0 top
CE3  12P_0402_50V8J  [C_0402]  37.72 80.68 270 top
CE4  12P_0402_50V8J  [C_0402]  35.96 80.67 180 top
CE5  10U_0603_6.3V6M  [C_0603]  42.42 86.2 180 top
CE6  0.1U_0402_10V7K  [C_0402]  30.72 74.86 180 top
CE7  1000P_0402_50V7K  [C_0402]  30.23 67.13 90 top
CE8  1000P_0402_50V7K  [C_0402]  41.52 85.12 0 top
CE9  0.1U_0402_25V6  [C_0402]  39.18 59.03 270 top
CE10  0.1U_0402_25V6  [C_0402]  52 60.16 0 top
CE11  0.1U_0402_25V6  [C_0402]  52.31 69.24 0 top
CE12  0.1U_0402_25V6  [C_0402]  46.1 80.21 90 top
CE13  0.1U_0402_25V6  [C_0402]  40.52 79.77 90 top
CE14  0.1U_0402_10V7K  [C_0402]  38.6 79.78 0 top
CE15  0.1U_0402_25V6  [C_0402]  44.13 59.41 270 top
CE16  100P_0402_50V8J  [C_0402]  31.1 61.65 180 top
CE17  0.1U_0402_25V6  [C_0402]  52.06 78.45 0 top
CE19  0.047U_0402_16V4Z  [C_0402]  52.01 61.04 90 top
CE20  0.1U_0402_25V6  [C_0402]  31.12 68.05 270 top
CE21  0.1U_0402_25V6  [C_0402]  43.31 84.18 270 top
CE22  0.1U_0402_10V7K  [C_0402]  47.12 59.35 270 top
CE23  0.1U_0402_25V6  [C_0402]  31.12 65.38 270 top
CE24  1U_0402_16V6K  [C_0402]  28.99 68.08 270 top
CE25  2200P_0402_25V7K  [C_0402]  44.24 81.45 90 top
CE26  47P_0402_50V8J  [C_0402]  50.55 59.03 270 top
CE28  220P_0402_50V8J  [C_0402]  38.29 59.03 270 top
CE30  2200P_0402_25V7K  [C_0402]  41.45 79.72 0 top
CE31  1000P_0402_50V7K  [C_0402]  52 64.61 0 top
CE32  100P_0402_50V8J  [C_0402]  32.76 78.83 0 top
CE33  2.2U_0402_6.3V6M  [C_0402]  33.59 79.77 90 top
CE35  33P_0402_50V8J  [C_0402]  45.75 56.73 90 top
CI1  0.1U_0402_10V7K  [C_0402]  20.62 100.37 180 bottom
CI2  0.1U_0402_10V7K  [C_0402]  20.62 99.48 180 bottom
CI3  0.1U_0402_10V7K  [C_0402]  20.62 102.21 180 bottom
CI4  0.1U_0402_10V7K  [C_0402]  20.62 101.32 180 bottom
CI5  0.1U_0402_10V7K  [C_0402]  20.62 98.52 180 bottom
CI6  0.1U_0402_10V7K  [C_0402]  20.62 97.64 180 bottom
CI7  0.1U_0402_10V7K  [C_0402]  20.62 96.68 180 bottom
CI8  0.1U_0402_10V7K  [C_0402]  20.62 95.79 180 bottom
CI9  .1U_0402_16V7K  [C_0402]  15.91 103.36 90 top
CL1  0.1U_0402_10V7K  [C_0402]  29.57 88.09 180 top
CL2  0.1U_0402_10V7K  [C_0402]  29.57 88.98 180 top
CL3  0.1U_0402_10V7K  [C_0402]  29.57 85.8 180 top
CL4  0.1U_0402_10V7K  [C_0402]  29.57 86.69 180 top
CL5  .1U_0402_16V7K  [C_0402]  20.18 83.96 180 top
CL6  .1U_0402_16V7K  [C_0402]  26.45 83.68 90 bottom
CL7  .1U_0402_16V7K  [C_0402]  20.18 81.85 180 top
CL8  .1U_0402_16V7K  [C_0402]  22.89 90.53 90 top
CL9  1U_0402_6.3V6K  [C_0402]  25.1 102.55 0 top
CL10  12P_0402_50V8J  [C_0402]  19.2 87.65 0 top
CL11  12P_0402_50V8J  [C_0402]  19.2 84.98 0 top
CL12  0.01U_0402_16V7K  [C_0402]  25.64 61.53 180 bottom
CL13  33P_1206_2KV8J  [C_1206]  21.18 76.91 0 bottom
CL15  .1U_0402_16V7K  [C_0402]  20.61 90.41 90 top
CL18  .1U_0402_16V7K  [C_0402]  23.91 83.04 90 bottom
CL19  .1U_0402_16V7K  [C_0402]  23.96 91.88 0 top
CL20  .1U_0402_16V7K  [C_0402]  28.66 84.77 0 top
CL22  1U_0402_10V6K  [C_0402]  23.96 90.1 0 top
CL23  .1U_0402_16V7K  [C_0402]  23.96 90.99 0 top
CL24  4.7U_0402_6.3V6M  [C_0402]  20.18 80.7 180 top
CL25  4.7U_0402_6.3V6M  [C_0402]  28.67 83.62 0 top
CM1  4.7U_0402_6.3V6M  [C_0402]  146.1 38.48 180 bottom
CM2  0.1U_0402_25V6  [C_0402]  146.78 35.82 270 bottom
CM3  4.7U_0402_6.3V6M  [C_0402]  155.79 35.11 0 top
CM4  0.1U_0402_25V6  [C_0402]  155.79 36.13 0 top
CM5  0.1U_0402_25V6  [C_0402]  145.83 34.91 90 bottom
CM6  100P_0402_50V8J  [C_0402]  147.83 33.99 90 bottom
CM7  0.1U_0402_16V7K  [C_0402]  149.23 28.46 90 top
CM8  22P_0402_50V8J  [C_0402]  151.08 37.62 180 bottom
CS1  0.01U_0402_50V7K  [C_0402]  179.74 31.81 0 bottom
CS2  0.01U_0402_50V7K  [C_0402]  179.74 32.7 0 bottom
CS3  0.01U_0402_50V7K  [C_0402]  179.74 33.59 0 bottom
CS4  0.01U_0402_50V7K  [C_0402]  179.74 34.48 0 bottom
CS5  1000P_0402_50V7K  [C_0402]  185.84 37.81 90 bottom
CS6  0.1U_0402_25V6K  [C_0402]  186.72 37.81 90 bottom
CS7  10U_0603_10V6M  [C_0603]  184.5 37.74 90 bottom
CS8  1U_0402_10V6K  [C_0402]  179.61 40.5 90 bottom
CS9  0.01U_0402_50V7K  [C_0402]  193.77 61.02 270 bottom
CS10  0.01U_0402_50V7K  [C_0402]  192.88 61.02 270 bottom
CS11  0.01U_0402_50V7K  [C_0402]  190.79 61.02 270 bottom
CS12  0.01U_0402_50V7K  [C_0402]  189.9 61.02 270 bottom
CS13  1000P_0402_50V7K  [C_0402]  193.04 65.83 90 top
CS14  0.1U_0402_25V6K  [C_0402]  192.1 65.83 90 top
CS15  10U_0603_10V6M  [C_0603]  189.84 66.12 90 top
CS16  0.22U_0402_16V7K  [C_0402]  37.06 36.97 270 bottom
CS17  0.22U_0402_16V7K  [C_0402]  36 36.97 270 bottom
CS18  0.22U_0402_16V7K  [C_0402]  34.08 36.97 270 bottom
CS19  0.22U_0402_16V7K  [C_0402]  33.19 36.97 270 bottom
CS20  0.22U_0402_16V7K  [C_0402]  31.09 36.97 270 bottom
CS21  0.22U_0402_16V7K  [C_0402]  30.2 36.97 270 bottom
CS22  0.22U_0402_16V7K  [C_0402]  28.36 36.97 270 bottom
CS23  0.22U_0402_16V7K  [C_0402]  27.47 36.97 270 bottom
CS24  10U_0805_25V6K~D  [C_0805]  44.4 31.81 0 bottom
CS25  1U_0402_6.3V6K~D  [C_0402]  38.01 26.93 270 top
CS26  0.1U_0402_25V6K~D  [C_0402]  20.82 27.03 180 top
CS27  1000P_0402_50V7K~D  [C_0402]  35.86 26.93 270 top
CS29  0.1U_0402_25V6K  [C_0402]  193.14 41.54 270 top
CS30  10U_0805_10V6K  [C_0805]  194.47 41.8 270 top
CS33  47U_0805_6.3V6M  [C_0805]  24.15 28.66 0 top
CS34  47U_0805_6.3V6M  [C_0805]  24.15 30.41 0 top
CS35  22U_0603_6.3V6M  [C_0603]  37.25 29.64 90 top
CS36  22U_0603_6.3V6M  [C_0603]  21.15 25.92 180 top
CT55  0.1U_0402_10V7K  [C_0402]  214.71 38.29 0 top
CT56  0.1U_0402_10V7K  [C_0402]  214.71 37.4 0 top
CT57  0.1U_0402_10V7K  [C_0402]  214.71 36.38 0 top
CT58  0.1U_0402_10V7K  [C_0402]  214.71 35.49 0 top
CT59  0.1U_0402_10V7K  [C_0402]  214.71 34.48 0 top
CT60  0.1U_0402_10V7K  [C_0402]  214.71 33.59 0 top
CU1  .1U_0402_16V7K  [C_0402]  24.18 55.07 180 bottom
CU2  .1U_0402_16V7K  [C_0402]  24.18 54.18 180 bottom
CU3  .1U_0402_16V7K  [C_0402]  25.67 38.49 180 bottom
CU4  .1U_0402_16V7K  [C_0402]  25.67 37.6 180 bottom
CU5  1U_0201_6.3V6M  [C_0201]  23.78 42.78 90 bottom
CU6  4.7U_0402_6.3V6M  [C_0402]  18.58 56.9 270 bottom
CU8  22U_0603_6.3V6M  [C_0603]  18.77 58.22 90 bottom
CU9  22U_0603_6.3V6M  [C_0603]  20.04 58.22 90 bottom
CU10  100U_A_6.3VM_R70M  [C_A]  21.81 57.74 90 bottom
CU11  4.7U_0402_6.3V6M  [C_0402]  17.26 39.17 180 bottom
CU13  22U_0603_6.3V6M  [C_0603]  18.87 40.57 0 bottom
CU14  22U_0603_6.3V6M  [C_0603]  17.65 40.57 180 bottom
CU15  100U_A_6.3VM_R70M  [C_A]  18.64 42.6 180 bottom
CU16  1U_0201_6.3V6M  [C_0201]  200.36 41.27 0 bottom
CU17  22U_0603_6.3V6M  [C_0603]  201.15 39.2 0 bottom
CW1  .1U_0402_16V7K  [C_0402]  82.01 127.46 90 bottom
CW2  .1U_0402_16V7K  [C_0402]  81.12 127.46 90 bottom
CW3  .1U_0402_16V7K  [C_0402]  71.28 125.2 90 top
CW4  .1U_0402_16V7K  [C_0402]  72.3 125.2 90 top
CW5  10U_0603_6.3V6M  [C_0603]  73.44 124.84 90 top
CW6  10U_0402_6.3V6M  [C_0402]  71.2 137.73 0 top
CW7  .1U_0402_16V7K  [C_0402]  67.93 121.34 180 top
CW8  .1U_0402_16V7K  [C_0402]  67.93 122.23 180 top
CW9  10P_0402_50V8J  [C_0402]  71.2 138.87 0 top
CX1  10U_0402_6.3V6M  [C_0402]  108.57 37.9 180 bottom
CX2  0.1U_0402_10V7K  [C_0402]  108.57 38.79 180 bottom
CX3  0.1U_0402_10V7K  [C_0402]  108.78 43.6 270 bottom
CX4  10U_0402_6.3V6M  [C_0402]  108.78 44.46 90 bottom
CX5  10U_0402_6.3V6M  [C_0402]  116.77 39.71 0 bottom
CX6  0.1U_0402_10V7K  [C_0402]  115.17 41.71 180 top
CX7  0.1U_0402_10V7K  [C_0402]  115.17 40.19 180 top
CZ1  0.1U_0402_10V7K  [C_0402]  150.62 67.79 270 top
CZ2  0.1U_0402_10V7K  [C_0402]  145.37 66.19 180 top
CZ3  470P_0402_50V7K  [C_0402]  146.74 68.48 0 top
CZ4  1U_0402_6.3V6K  [C_0402]  150.07 62.03 0 top
CZ5  0.1U_0402_10V7K  [C_0402]  150.07 60.12 0 top
CZ6  0.1U_0402_10V7K  [C_0402]  145.56 58 180 top
CZ7  0.1U_0402_10V7K  [C_0402]  150.07 61.14 0 top
CZ8  0.1U_0402_25V6  [C_0402]  144.36 47.43 0 top
CZ9  0.1U_0402_10V7K  [C_0402]  128.79 133.02 270 top
CZ10  470P_0402_50V7K  [C_0402]  127.9 133.02 270 top
CZ11  470P_0402_50V7K  [C_0402]  126.4 133.02 270 top
CZ12  0.1U_0402_10V7K  [C_0402]  125.51 133.02 270 top
CZ21  1U_0402_6.3V6K  [C_0402]  150.62 65.1 90 top
CZ22  0.1U_0402_10V7K  [C_0402]  149.56 68.48 180 top
CZ23  1U_0402_6.3V6K  [C_0402]  128.05 137.89 90 top
CZ25  1U_0402_6.3V6K  [C_0402]  125.76 137.89 90 top
D1  -  [BAS40C_SOT23-3]  89.16 37.78 270 top
D3  -  [BAT54C-7-F_SOT23-3]  219.24 52.15 180 top
D4  -  [BAT54C-7-F_SOT23-3]  211.36 49.31 0 top
D5  -  [RB551V-30_SOD323-2]  214.66 45.77 270 top
D6  -  [RB551V-30_SOD323-2]  124.94 26.32 90 top
D7  -  [RB751S40T1G_SOD523-2]  54.65 30.92 180 top
DA1  -  [L03ESDL5V0CC3-2_SOT23-3]  18.51 3.28 90 top
DA2  -  [L03ESDL5V0CC3-2_SOT23-3]  21.03 3.26 270 top
DA3  -  [BAT54C-7-F_SOT23-3]  29.79 27.11 90 top
DA4  -  [L03ESDL5V0CC3-2_SOT23-3]  17 19.01 0 bottom
DA5  AZ5123-02S.R7G_SOT23-3  [AZ5123-02SPR7G_SOT23-3]  19.62 8.57 90 top
DA6  -  [AZC199-02SPR7G_SOT23-3]  209.14 44.39 0 bottom
DA7  -  [L03ESDL5V0CC3-2_SOT23-3]  17.05 19.01 180 top
DE1  AZ5125-01H.R7G_SOD523-2  [AZ5125-01HPR7G_SOD523-2]  53.98 77.44 90 top
DI1  -  [BAW56W_SOT323-3]  23.11 109.64 90 bottom
DZ2  -  [RB751S40T1G_SOD523-2]  151.07 56.92 90 top
DZ3  -  [RB751S40T1G_SOD523-2]  104.45 47.79 0 top
DZ4  -  [RB751S40T1G_SOD523-2]  118.91 40.02 270 top
DZ5  -  [RB751S40T1G_SOD523-2]  152.53 66.94 90 top
EC2301  0.1U_0402_25V6  [C_0402]  19.72 19.87 180 top
EC2302  0.1U_0402_25V6  [C_0402]  25.69 23.99 90 top
EC2901  1000P_0402_50V7K  [C_0402]  222.61 63.71 0 top
EC2902  .1U_0402_16V7K  [C_0402]  219.58 62.5 180 top
EC3001  .1U_0402_16V7K  [C_0402]  92.62 32.55 270 top
EC3002  .1U_0402_16V7K  [C_0402]  94.51 32.41 0 top
EC3003  0.1U_0402_25V6  [C_0402]  21.31 7.44 270 top
ED2901  -  [L03ESDL5V0CC3-2_SOT23-3]  220.21 66.59 180 top
EU2601  AZ1045-04F.R7G DFN2510P10E ESD  [L05ESDL5V0NA-4_SLP2510P8-10-9]  18.65 52.67 270 bottom
EU2602  -  [AZC199-02SPR7G_SOT23-3]  22.03 49.86 270 bottom
EU2603  AZ1045-04F.R7G DFN2510P10E ESD  [L05ESDL5V0NA-4_SLP2510P8-10-9]  20.2 36.16 270 bottom
EU2604  -  [AZC199-02SPR7G_SOT23-3]  18.68 32.7 270 top
EU2701  -  [AZC199-02SPR7G_SOT23-3]  221.14 34.2 180 bottom
EU4012  -  [AZC199-02SPR7G_SOT23-3]  202.7 42.73 90 bottom
F1  1.5A_24V_SMD1812P150TF-24  [F_SMD1812P150TF-24]  204.56 56.95 0 bottom
F2  S FUSE T0603FF1000TM 1A 65V UL FAST  [F_SMD1812P110TF-24]  222.04 44.81 180 top
F3  0.5A_13.2V_MF-NSMF050-2  [F_MF-NSMF050-2]  90.82 27.87 180 top
FD1  FIDUCAL  [FIDUCIAL_C40M80]  13.88 128.07 0 top
FD2  FIDUCAL  [FIDUCIAL_C40M80]  222.42 26.47 0 top
FD3  FIDUCAL  [FIDUCIAL_C40M80]  16.42 127.82 180 bottom
FD4  FIDUCAL  [FIDUCIAL_C40M80]  219.62 40.95 180 bottom
FI1  1.5A_6V_1206L150PR~D  [F_1206L150PR]  17.56 103.18 90 top
H1  HOLEA  [H_3P0]  6.85 130.5 0 top
H2  HOLEA  [H_3P0]  7.9 85.8 0 top
H3  HOLEA  [H_3P0]  8 41.2 0 top
H4  HOLEA  [H_3P0]  141.55 27.1 0 top
H5  HOLEA  [H_3P0]  207.45 63.85 0 top
H6  HOLEA  [H_5P0]  169.05 109.5 0 top
H7  HOLEA  [H_3P0]  99 154 0 top
H8  HOLEA  [H_3P3]  6.9 112.6 0 top
H12  HOLEA  [H_3P2]  45.5 130.8 0 top
H13  HOLEA  [H_3P0X4P0]  213.85 65.5 90 top
H14  HOLEA  [H_5P6N]  19.1 111.3 90 top
HCPU1  HOLEA  [H_4P0X3P7]  113.08 110.41 0 top
HCPU2  HOLEA  [H_3P7]  137.38 110.41 0 top
HCPU3  HOLEA  [H_4P0]  113.08 49.41 0 top
HCPU4  HOLEA  [H_4P0X3P7]  137.38 49.41 90 top
JCMOS1  SHORT PADS~D  [SHORTPADS]  89.71 49.22 270 bottom
JDEG1  JXT_FP241AH-010GAAM  [JXT_FP241AH-010GAAM_10P]  46 94.08 180 top
JDIMM1  DEREN_40-42271-26001RHF  [LOTES_ADDR0206-P001A02_260P]  79.15 112.24 90 bottom
JDIMM2  DEREN_40-42261-26001RHF  [LOTES_ADDR0205-P001A02_260P]  66.45 112.24 270 bottom
JEDP1  ACES_51540-04001-P01  [ACES_51540-04001-P01_40P]  212.37 60.45 270 bottom
JESPI1  JXT_FP241AH-010GAAM  [JXT_FP241AH-010GAAM_10P]  111.07 30.01 180 bottom
JFAN1  ACES_50224-00401-001  [ACES_50224-00401-001_4P]  179.96 68.62 45 bottom
JFP  ACES_51522-00601-001  [ACES_51522-00601-001_6P-NPM]  220 30.6 180 bottom
JFP1  ACES_51522-00801-001  [ACES_51522-00801-001_8P]  221 30.6 180 bottom
JHDD1  ACES_51625-01201-001  [ACES_51625-01201-001_12P]  190.2 35.7 180 bottom
JHDMI1  CONCR_099AKAC19NBLCNF  [ACON_HMRF6-AK120C_19P-T]  11.05 92.35 90 bottom
JHP1  YUQIU_PJ753-F07J1BE-B  [YUQIU_PJ753-F07J1BE-B_7P-T]  12.65 7.9 90 bottom
JIOB1  ACES_51524-0160N-001  [ACES_51524-0160N-001_16P]  213.2 36.8 180 bottom
JKB1  HEFEN_AFB02-S30F1A-HF  [HEFEN_AFB02-S30F1A-HF_30P-T]  59.75 34.05 180 bottom
JKBBL1  ACES_51575-00401-001  [ACES_51575-00401-001_4P]  95.05 34.51 180 bottom
JLAN1  SANTA_130460-N  [SINGA_2RJ3076-078211F_8P-T]  12.95 77.72 90 bottom
JODD1  ACES_50673-0120N-P01  [ACES_50673-0120N-P01_12P]  185.2 64.3 180 bottom
JP1  -  [JUMP_43X79]  146.09 55.65 180 top
JP2  PAD-OPEN1x1m  [JUMP_43X39]  145 68.3 270 top
JP4  -  [JUMP_43X39]  150.32 65.59 180 bottom
JP5  -  [JUMP_43X79]  181.69 38.52 270 bottom
JP6  -  [JUMP_43X79]  182.54 69.78 0 top
JP10  -  [JUMP_43X79]  28.78 45.52 180 bottom
JP11  2MM  [JUMP_43X39]  22.7 98.28 90 top
JPWR1  JXT_FP226H-004S1AM  [JXT_FP226H-004S1AM_4P]  221.2 63.65 0 bottom
JSPK1  ACES_50224-00401-001  [ACES_50224-00401-001_4P]  16.4 5.88 180 bottom
JSSD1  LCN_DAN05-67306-0103  [LCN_DAN05-67306-0103_75P]  39.37 34.03 180 bottom
JTP1  ACES_51524-0080N-001  [ACES_51524-0080N-001_8P]  125.05 30.5 180 bottom
JUSB1  ACON_TARAN-9R1391  [ACON_TARAN-9R1391_9P]  15.88 56.65 90 bottom
JUSB2  ACON_TARAN-9R1391  [ACON_TARAN-9R1391_9P]  15.88 32.75 90 bottom
JVGA  ACES_51625-01601-001  [ACES_51625-01601-001_16P-T]  217.65 38.75 90 top
JWLAN1  LCN_DAN05-67306-0100  [LCN_DAN05-67306-0100_75P]  79.03 121.55 90 bottom
L1  BLM15BD601SN1D_2P  [MURAT_BLM15BD601SN1D_2P]  126.53 69.39 270 top
L2  BLM15BD601SN1D_2P  [MURAT_BLM15BD601SN1D_2P]  122.21 68.89 0 top
L3  MCM1012B900F06BP_4P  [INPAQ_MCM1012B900F06BP_4P]  210.1 47.53 270 bottom
L4  MCM1012B900F06BP_4P  [INPAQ_MCM1012B900F06BP_4P-NPM]  210.79 39.17 90 bottom
L5  BLM15PX221SN1D_2P  [MURAT_BLM15PX221SN1D_2P]  36.27 10.98 180 top
LED1  LTW-295DSKS-5A_YEL-WHITE~D  [LED_LTW-295DSKS-5A_4P]  3.25 133.05 270 bottom
LI1  HCM1012GH900BP_4P  [INPAQ_HCM1012GH900BP_4P-NPM]  16.87 99.67 0 bottom
LI2  HCM1012GH900BP_4P  [INPAQ_HCM1012GH900BP_4P-NPM]  16.87 101.51 0 bottom
LI3  HCM1012GH900BP_4P  [INPAQ_HCM1012GH900BP_4P-NPM]  16.87 96.05 0 bottom
LI4  HCM1012GH900BP_4P  [INPAQ_HCM1012GH900BP_4P-NPM]  16.87 97.89 0 bottom
LU1  MCM1012B900F06BP_4P  [INPAQ_MCM1012B900F06BP_4P]  23.21 47.64 0 bottom
LU2  HCM1012GH900BP_4P  [INPAQ_HCM1012GH900BP_4P-NPM]  20.94 54.37 0 bottom
LU3  HCM1012GH900BP_4P  [INPAQ_HCM1012GH900BP_4P-NPM]  20.94 52.6 0 bottom
LU4  MCM1012B900F06BP_4P  [INPAQ_MCM1012B900F06BP_4P]  22.94 33.06 0 top
LU5  HCM1012GH900BP_4P  [INPAQ_HCM1012GH900BP_4P-NPM]  22.42 37.8 0 bottom
LU6  HCM1012GH900BP_4P  [INPAQ_HCM1012GH900BP_4P-NPM]  22.42 36.02 0 bottom
LU8  MCM1012B900F06BP_4P  [INPAQ_MCM1012B900F06BP_4P]  208.88 38.98 90 bottom
LU9  MCM1012B900F06BP_4P  [INPAQ_MCM1012B900F06BP_4P]  207.1 38.98 90 bottom
NOREF  -  []  137.38 110.41 0 top
NOREF#2  -  []  6.9 112.6 0 top
NOREF#3  -  []  94.72 -24.45 0 top
NOREF#4  -  []  6.85 130.5 0 top
NOREF#5  -  []  99 154 0 top
NOREF#6  -  []  45.5 130.8 0 top
NOREF#7  -  []  7.9 85.8 0 top
NOREF#8  -  []  -88.4 135.94 0 top
NOREF#9  -  []  65.19 31.26 0 top
NOREF#10  -  []  170.54 109.56 0 top
NOREF#11  -  []  113.08 110.41 0 top
NOREF#12  -  []  40.67 32.01 0 top
NOREF#13  -  []  8 41.2 0 top
NOREF#14  -  []  207.45 63.85 0 top
NOREF#15  -  []  141.55 27.1 0 top
NOREF#16  -  []  63.98 38.67 0 top
NOREF#17  -  []  213.85 65.5 0 top
NOREF#18  -  []  90.89 86.37 0 top
NOREF#19  -  []  59.28 144.08 0 top
NOREF#20  -  []  20.67 126.8 0 top
NOREF#21  -  []  113.08 49.41 0 top
NOREF#22  -  []  91.17 103.82 0 top
NOREF#23  -  []  137.38 49.41 0 top
NOREF#24  -  []  91.17 71.94 0 top
NOREF#25  -  []  96.05 52.34 180 bottom
NOREF#26  -  []  88.93 -13.34 180 bottom
NOREF#27  -  []  129.45 112.01 90 bottom
PBATT1  -  [ACES_50458-01001-P01_10P-T]  172.95 40 180 bottom
PC1  1000P_0402_50V7K  [C_0402]  94.93 147.33 90 top
PC2  2200P_0402_25V7K  [C_0402]  93.97 147.33 90 top
PC3  1000P_0402_50V7K  [C_0402]  96.96 147.3 90 top
PC4  2200P_0402_25V7K  [C_0402]  97.9 147.3 90 top
PC11  0.01U_0402_25V7K  [C_0402]  175.85 42.81 270 bottom
PC12  1000P_0402_50V7K  [C_0402]  174.02 42.81 270 bottom
PC13  .1U_0402_16V7K  [C_0402]  117.98 139.68 270 top
PC14  .1U_0402_16V7K  [C_0402]  31.02 60.71 270 top
PC15  10P_0402_25V8J  [C_0402]  94.06 143.57 0 bottom
PC301  1000P_0402_25V8J  [C_0402]  102.31 141.93 90 bottom
PC302  2200P_0402_50V7K  [C_0402]  103.22 141.95 90 bottom
PC303  4.7U_0805_25V6K  [C_0805]  104.57 141.77 90 bottom
PC304  4.7U_0805_25V6K  [C_0805]  104.57 141.77 90 top
PC305  0.1U_0402_25V6  [C_0402]  101.39 141.93 90 bottom
PC306  1000P_0402_25V8J  [C_0402]  106 142.27 90 bottom
PC307  0.1U_0402_10V7K  [C_0402]  103.51 136.01 270 bottom
PC308  4.7U_0402_6.3V6M  [C_0402]  111.36 137.48 0 bottom
PC309  680P_0603_50V7K  [C_0603]  107.1 139.31 90 top
PC310  22U_0805_6.3V6M  [C_0805]  113.09 133.36 90 top
PC311  22U_0805_6.3V6M  [C_0805]  114.92 134.88 90 bottom
PC312  22U_0805_6.3V6M  [C_0805]  116.67 134.89 90 bottom
PC313  22U_0805_6.3V6M  [C_0805]  115.01 131.45 270 bottom
PC314  22U_0805_6.3V6M  [C_0805]  118.22 133.41 90 top
PC315  1000P_0402_25V8J  [C_0402]  112.11 139.39 0 bottom
PC501  1000P_0402_25V8J  [C_0402]  152.71 142.34 0 bottom
PC502  2200P_0402_50V7K  [C_0402]  152.71 141.44 0 bottom
PC503  10U_0805_25V6K  [C_0805]  154.95 138.22 90 bottom
PC504  10U_0805_25V6K  [C_0805]  154.95 138.22 90 top
PC505  0.1U_0402_25V6  [C_0402]  152.71 140.52 0 bottom
PC506  1000P_0402_25V8J  [C_0402]  152.71 139.62 0 bottom
PC507  0.1U_0402_10V7K  [C_0402]  154.42 134.71 0 bottom
PC508  4.7U_0402_6.3V6M  [C_0402]  161.46 134.83 0 bottom
PC509  680P_0603_50V7K  [C_0603]  156.5 137.79 90 top
PC510  22U_0805_6.3V6M  [C_0805]  161.61 125.42 0 bottom
PC511  22U_0805_6.3V6M  [C_0805]  161.62 123.69 0 bottom
PC512  22U_0805_6.3V6M  [C_0805]  155.06 124.01 180 top
PC513  22U_0805_6.3V6M  [C_0805]  161.62 121.98 0 bottom
PC514  22U_0805_6.3V6M  [C_0805]  155.06 125.79 180 top
PC515  4.7U_0402_6.3V6M  [C_0402]  161.45 135.77 0 bottom
PC516  4.7U_0402_6.3V6M  [C_0402]  112.38 142.04 180 bottom
PC517  1000P_0402_25V8J  [C_0402]  162.28 138.31 0 bottom
PC1801  22U_0603_6.3V6M  [C_0603]  169.33 46.78 270 bottom
PC1802  22U_0603_6.3V6M  [C_0603]  155.23 47.86 90 bottom
PC1803  22U_0603_6.3V6M  [C_0603]  155.23 45.7 270 bottom
PC1804  22U_0603_6.3V6M  [C_0603]  155.23 47.86 90 top
PC1805  0.1U_0402_10V7K  [C_0402]  164.96 49.38 180 bottom
PC1806  680P_0402_50V7K  [C_0402]  163.66 45.51 0 top
PC1807  22P_0402_50V8J  [C_0402]  170.16 49.13 180 bottom
PC2501  10U_0805_10V6K  [C_0805]  51.82 26.34 0 bottom
PC2502  10U_0805_10V6K  [C_0805]  51.68 35.81 180 bottom
PC2503  0.1U_0402_10V6K  [C_0402]  56.3 26.74 270 bottom
PC2504  1U_0402_6.3V6K  [C_0402]  49.95 28.77 270 bottom
PC2505  0.01U_0402_25V7K  [C_0402]  53.63 35.1 0 bottom
PCA01  10U_0805_25V6K  [C_0805]  166.3 65.78 180 bottom
PCA02  10U_0805_25V6K  [C_0805]  166.3 65.78 180 top
PCA03  0.1U_0402_25V6  [C_0402]  164.49 58.46 90 bottom
PCA04  2200P_0402_50V7K  [C_0402]  165.4 58.46 90 bottom
PCA05  1000P_0402_50V7K  [C_0402]  166.32 58.46 90 bottom
PCA06  1000P_0402_50V7K  [C_0402]  167.23 58.46 90 bottom
PCA07  0.22U_0603_16V7K  [C_0603]  169.33 62.78 180 bottom
PCA08  2.2U_0603_16V6K  [C_0603]  170.85 58.91 180 bottom
PCA09  680P_0603_50V7K  [C_0603]  162.72 58.99 0 top
PCA101  22U_0603_6.3V6M  [C_0603]  124.65 73.18 90 top
PCA102  22U_0603_6.3V6M  [C_0603]  125.86 73.18 90 top
PCA103  22U_0603_6.3V6M  [C_0603]  122.37 73.31 180 top
PCA104  22U_0603_6.3V6M  [C_0603]  123.45 73.18 90 top
PCA105  22U_0603_6.3V6M  [C_0603]  129.54 73.18 90 top
PCA106  22U_0603_6.3V6M  [C_0603]  155.36 60.45 180 bottom
PCA107  22U_0603_6.3V6M  [C_0603]  155.36 62.97 180 bottom
PCA108  22U_0603_6.3V6M  [C_0603]  155.36 61.7 180 bottom
PCA109  22U_0603_6.3V6M  [C_0603]  128.34 73.18 90 top
PCA110  1U_0201_6.3V6M  [C_0201]  132.27 75.49 90 top
PCA111  1U_0201_6.3V6M  [C_0201]  127.38 72.95 90 top
PCA112  1U_0201_6.3V6M  [C_0201]  127.38 74.16 90 top
PCA113  1U_0201_6.3V6M  [C_0201]  126.81 72.95 90 top
PCA114  1U_0201_6.3V6M  [C_0201]  126.81 74.16 90 top
PCA115  1U_0201_6.3V6M  [C_0201]  122.85 75.46 180 top
PCA116  1U_0201_6.3V6M  [C_0201]  122.24 74.28 90 top
PCA117  10U_0402_6.3V6M  [C_0402]  154.15 67.48 90 bottom
PCA118  10U_0402_6.3V6M  [C_0402]  155.16 67.48 90 bottom
PCB01  5600P_0402_25V7K  [C_0402]  178.96 65.18 0 top
PCB02  0.1U_0402_25V6  [C_0402]  181.95 63.81 90 top
PCB03  10U_0805_25V6K  [C_0805]  190.86 51.8 0 bottom
PCB04  10U_0805_25V6K  [C_0805]  190.86 50.08 0 top
PCB05  10U_0805_25V6K  [C_0805]  190.86 50.08 0 bottom
PCB06  10U_0805_25V6K  [C_0805]  190.86 51.8 0 top
PCB07  0.1U_0402_25V7K  [C_0402]  191.72 54.14 0 bottom
PCB08  2200P_0402_25V7K  [C_0402]  191.72 53.22 0 bottom
PCB09  1000P_0402_25V8J  [C_0402]  190.72 48.69 270 bottom
PCB10  1000P_0402_25V8J  [C_0402]  191.64 48.68 270 bottom
PCB11  0.1U_0402_25V6  [C_0402]  202.23 54.41 180 bottom
PCB12  0.01UF_0402_25V7K  [C_0402]  204.05 54.35 0 top
PCB13  0.22U_0603_25V7K  [C_0603]  199.82 55.75 270 bottom
PCB14  0.1U_0402_25V7K  [C_0402]  179.98 52.76 0 top
PCB15  0.22U_0402_16V7K  [C_0402]  194.65 51.3 0 bottom
PCB16  1U_0402_16V6K  [C_0402]  195.55 49.44 180 bottom
PCB17  1U_0402_16V6K  [C_0402]  195.55 50.36 180 bottom
PCB18  680P_0603_50V7K  [C_0603]  188.06 46.73 0 top
PCB19  4.7U_0805_25V6K  [C_0805]  175.26 49.84 180 top
PCB20  10U_0805_25V6K  [C_0805]  177.25 42.69 270 bottom
PCB21  4.7U_0805_25V6K  [C_0805]  175.26 48.06 180 top
PCB22  0.1U_0402_25V7K  [C_0402]  174.96 42.81 270 bottom
PCB23  10U_0805_25V6K  [C_0805]  175.26 48.06 180 bottom
PCB24  10U_0805_25V6K  [C_0805]  175.26 49.84 180 bottom
PCB25  0.1U_0402_25V7K  [C_0402]  205.89 49.72 0 bottom
PCB26  2200P_0402_25V7K  [C_0402]  205.9 48.84 270 bottom
PCB27  1U_0603_25V6  [C_0603]  196.38 48.26 180 bottom
PCB28  0.047U_0402_25V7K  [C_0402]  204.57 47.14 270 top
PCB29  560P_0402_50V7K  [C_0402]  202.73 46.43 270 top
PCB30  0.015U_0402_25V7K  [C_0402]  203.46 45.58 0 bottom
PCB31  10P_0402_50V8J  [C_0402]  200.94 46.41 0 top
PCB32  0.1U_0402_25V6  [C_0402]  199.16 46.41 0 top
PCC01  22U_0603_6.3V6M  [C_0603]  121.69 86.86 270 top
PCC02  22U_0603_6.3V6M  [C_0603]  122.9 86.86 270 top
PCC03  22U_0603_6.3V6M  [C_0603]  128.53 87.53 180 top
PCC04  22U_0603_6.3V6M  [C_0603]  128.53 86.26 180 top
PCC05  10U_0402_6.3V6M  [C_0402]  132.81 86.24 270 top
PCC6  10U_0402_6.3V6M  [C_0402]  131.92 86.24 270 top
PCG01  10U_0805_25V6K  [C_0805]  142.19 137.98 0 bottom
PCG02  10U_0805_25V6K  [C_0805]  142.19 136.2 0 bottom
PCG03  10U_0805_25V6K  [C_0805]  142.19 137.98 0 top
PCG04  10U_0805_25V6K  [C_0805]  142.19 136.2 0 top
PCG05  0.1U_0402_25V6  [C_0402]  145.8 139.56 270 bottom
PCG06  2200P_0402_50V7K  [C_0402]  144.91 139.56 270 bottom
PCG07  1000P_0402_50V7K  [C_0402]  147.62 139.56 270 bottom
PCG08  1000P_0402_50V7K  [C_0402]  146.73 139.56 270 bottom
PCG09  0.22U_0603_25V7K  [C_0603]  138.02 133.73 0 bottom
PCG10  1U_0402_16V6K  [C_0402]  139.47 131.28 180 bottom
PCG11  1U_0402_16V6K  [C_0402]  142.52 128.39 0 top
PCG12  680P_0603_50V8J  [C_0603]  145.96 132.46 90 top
PCG13  33U_D2_25VM_R40M  [C_EEFCX1E330R]  150.43 136.78 90 bottom
PCG14  33U_25V_M  [C_6P3X4P5-NPM]  150.43 136.38 270 bottom
PCG101  22U_0603_6.3V6M  [C_0603]  126.73 106.21 180 bottom
PCG102  22U_0603_6.3V6M  [C_0603]  128.2 104.8 0 bottom
PCG103  22U_0603_6.3V6M  [C_0603]  126.73 103.66 180 bottom
PCG104  22U_0603_6.3V6M  [C_0603]  128.2 103.56 0 bottom
PCG105  22U_0603_6.3V6M  [C_0603]  126.73 104.93 180 bottom
PCG106  22U_0603_6.3V6M  [C_0603]  133.51 126.17 90 top
PCG107  22U_0603_6.3V6M  [C_0603]  128.91 93.31 270 top
PCG108  22U_0603_6.3V6M  [C_0603]  128.2 106.07 0 top
PCG109  22U_0603_6.3V6M  [C_0603]  128.2 106.07 0 bottom
PCG110  22U_0603_6.3V6M  [C_0603]  130.18 93.31 270 top
PCG111  22U_0603_6.3V6M  [C_0603]  126.74 102.39 180 top
PCG112  22U_0603_6.3V6M  [C_0603]  128.2 104.8 0 top
PCG113  22U_0603_6.3V6M  [C_0603]  136.05 126.17 90 top
PCG114  22U_0603_6.3V6M  [C_0603]  132.24 126.17 90 top
PCG115  22U_0603_6.3V6M  [C_0603]  128.2 102.29 0 top
PCG116  22U_0603_6.3V6M  [C_0603]  125.1 93.31 270 top
PCG117  22U_0603_6.3V6M  [C_0603]  126.37 93.31 270 top
PCG118  22U_0603_6.3V6M  [C_0603]  126.73 104.93 180 top
PCG119  22U_0603_6.3V6M  [C_0603]  126.74 107.44 180 bottom
PCG120  22U_0603_6.3V6M  [C_0603]  127.64 93.31 270 top
PCG121  22U_0603_6.3V6M  [C_0603]  130.3 90.83 180 top
PCG122  22U_0603_6.3V6M  [C_0603]  125.1 90.89 270 top
